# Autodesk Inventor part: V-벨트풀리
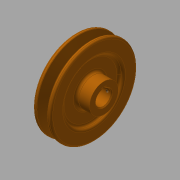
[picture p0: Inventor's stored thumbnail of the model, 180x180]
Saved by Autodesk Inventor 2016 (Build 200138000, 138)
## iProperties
Created: 2015-09
Part Number: V-벨트풀리
Material: 강철, 연강
Document SubType Name: Modeling
Designer: mduedu
Density: 7.86 g/cm^3
Mass: 779.014 g
Surface Area: 277.465 cm^2
Volume: 99.1112 cm^3
Appearance: 강철
Author: mduedu
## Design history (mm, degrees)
sketch "스케치1"
  geometry: L1 (-10, 0)-(10, 0); L2 (-10, 0)-(-10, 48); L3 (-10, 48)-(-5.976, 48); L4 (-5.976, 48)-(-2.154, 35.5); L5 (-2.154, 35.5)-(2.154, 35.5); L6 (2.154, 35.5)-(5.976, 48); L7 (5.976, 48)-(10, 48); L8 (10, 48)-(10, 0); L9 (0, 0)-(0, 35.5); L10 (-10, 43.5)-(10, 43.5); 3 further points
  constraints: 20 end point, 6 point on line, 3 perpendicular, 2 midpoint, 2 parallel, 2 symmetric about line, 1 coincident, 1 collinear, 1 equal length, 1 horizontal, 1 vertical, 1 vertical alignment
  dimensions: "d0" = 20 distance between parallel lines of L8 L2; "d2" = 96 diameter of L3 L1; "d3" = 87 diameter of L10 L1; "d4" = 4.5 distance between parallel lines of L10 L3 (derived); "d5" = 8 distance between parallel lines of L5 L10; "d6" = 9.2 distance of point (4.6, 43.5) point (-4.6, 43.5); "d7" = 34 deg angle of L6 L4
revolve "회전1" sketch "스케치1" stored, may be unused: angle "d8" = 90 deg
sketch "스케치2"
  geometry: C1 r 16 at (0, 0); 1 further point
  constraints: 1 centre point, 1 coincident
  dimensions: "d9" = 32 diameter of C1
extrude "돌출1" join sketch "스케치2" distance "d10" = 11; taper "d11" = 0 deg
fillet "모깎기1" dims "d12" = 1, "d13" = 0.5, "d14" = 2
sketch "스케치3"
  geometry: C1 r 16 at (0, 0) reference; C2 r 32 at (0, 0); 1 further point
  constraints: 1 centre point, 1 coincident
  dimensions: "d15" = 64 diameter of C2
extrude "돌출2" cut sketch "스케치3" distance "d16" = 4; taper "d17" = 0 deg
fillet "모깎기2" dims "d18" = 3
fillet "모깎기3" dims "d19" = 3
fillet "모깎기4" dims "d20" = 3
sketch "스케치4"
  geometry: C1 r 8.5 at (0, 0); 1 further point
  constraints: 1 centre point, 1 coincident
  dimensions: "d21" = 17 diameter of C1
extrude "돌출3" cut sketch "스케치4" stored distance "d22" = 4; taper "d23" = 0 deg
sketch "스케치5"
  geometry: L1 (-2.5, 8.124)-(2.5, 8.124); L2 (2.5, 8.124)-(2.5, 10.8); L3 (2.5, 10.8)-(-2.5, 10.8); L4 (-2.5, 10.8)-(-2.5, 8.124); A1 r 8.5 centre (0, 0) between (-2.5, 8.124) and (2.5, 8.124) reference; 2 further points
  constraints: 8 end point, 3 point on circle, 2 parallel, 1 horizontal, 1 perpendicular, 1 vertical alignment
  dimensions: "d24" = 5 distance of L2.end L3.end; "d26" = 19.3 distance from line of L3 point (0, -8.5)
extrude "돌출4" cut sketch "스케치5" stored distance "d27" = 4; taper "d28" = 0 deg
chamfer "모따기1" distance "d29" = 1; stored, may be unused: second distance "d30" = 2, angle "d31" = 45 deg
node "작업 평면1"
sketch "스케치6"
  geometry: L1 (-11, 16)-(-11, -16) reference; 2 further points
  constraints: 1 horizontal alignment
  dimensions: "d32" = 5 distance from line of point (-6, 0) L1
hole "구멍1" sketch "스케치6" at (-6, 0) diameter "d33" = 3.242; stored, may be unused: countersink angle "d37" = 90 deg, drill point angle "d39" = 118 deg; dims "d34" = 6, "d35" = 4, "d36" = 2, "d38" = 8
node "솔리드1"
mirror "대칭1"
